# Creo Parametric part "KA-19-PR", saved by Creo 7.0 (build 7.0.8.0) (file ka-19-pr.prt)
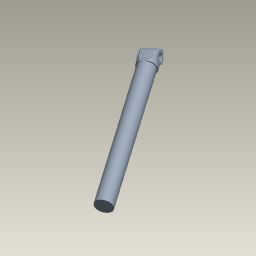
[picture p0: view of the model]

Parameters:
  PTC_COMMON_NAME = "ka-19-pr.prt"
  PTC_WM_REVISION = "A"
  PTC_WM_ITERATION = "1"
  PTC_WM_VERSION = "A.1"
  PTC_WM_LIFECYCLE_STATE = "Concept"
  PTC_WM_LIFECYCLE = "Life Cycle Schema Type 1"
  PTC_WM_LOCATION = "/Products/KA19_CN2215/CAD"
  PTC_WM_CREATED_BY = "Jörg Monien"
  PTC_WM_CREATED_ON = "2026-08-11"
  PTC_WM_MODIFIED_BY = "Jörg Monien"
  PTC_WM_MODIFIED_ON = "2026-08-11"
  PTC_WM_NAME = "ka-19-pr.prt"
  PTC_WM_NUMBER = "KA-19-PR.PRT"
  PDMREV = "A.1+"
  PDMRL = "Concept"
  PROI_REVISION = "A"
  PROI_VERSION = "1"
  PROI_RELEASE = "Concept"

Created from: START_PART.PRT

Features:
  1. datum plane "RIGHT"
  2. datum plane "TOP"
  3. datum plane "FRONT"
  4. coordinate system
  5. datum axis
  6. datum axis
  7. datum axis
  8. imported feature "Import Feature id 1049"
  9. extrusion "Extrude 1"

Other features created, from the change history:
  imported feature "Import Feature id 48"
  extrusion "Extrude 1"
  feature "Copy Geometry id 280"
  patch "Solidify 1"

Other named items: X-AXES, Y-AXES, Z-AXES, CS0

Layers: ANNOTATIONS, AXES, COSMETICS, CSYS, CURVES, EXT_COPY_GEOM, PLANES, POINTS, PUBLISHED_GEOM, QUILTS, SOLIDS, STARTUP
